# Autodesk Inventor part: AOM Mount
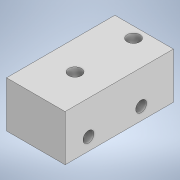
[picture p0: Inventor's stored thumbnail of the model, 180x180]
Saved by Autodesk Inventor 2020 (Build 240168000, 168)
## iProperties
Created: 2021-06
Part Number: AOM Mount
Material: Generic
Document SubType Name: Modeling
Designer: Sarah Bromley
Density: 1 g/cm^3
Appearance: Default
Author: Sarah Bromley
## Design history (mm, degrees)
sketch "Sketch1"
  geometry: L1 (-12.7, 23.5)-(12.7, 23.5); L2 (12.7, 23.5)-(12.7, -23.5); L3 (12.7, -23.5)-(-12.7, -23.5); L4 (-12.7, -23.5)-(-12.7, 23.5); L5 (-12.7, 23.5)-(12.7, -23.5); L6 (12.7, 23.5)-(-12.7, -23.5); 1 further point
  constraints: 12 end point, 2 midpoint, 2 parallel, 1 horizontal, 1 perpendicular
  dimensions: "d0" = 25.4 distance of L2.end L3.end; "d1" = 47 distance of L3.end L1.start
extrude "Extrusion1" new body sketch "Sketch1" stored distance "d2" = 20; taper "d3" = 0 deg
sketch "Sketch2"
  geometry: L1 (-12.7, -23.5)-(12.7, -23.5) reference; 2 further points
  dimensions: "d4" = 17 distance from line of point (0, -6.5) L1
hole "Hole1" sketch "Sketch2" at (0, -6.5) diameter "d5" = 3.264; stored, may be unused: countersink angle "d9" = 82 deg, drill point angle "d11" = 118 deg; dims "d6" = 6, "d7" = 5.558, "d8" = 10, "d10" = 8.8
pattern_linear "Rectangular Pattern1" dims "d14" = 25.4
sketch "Sketch3"
  geometry: L1 (0, 0)-(0, 20) reference; L2 (0, 0)-(-47, 0) reference; 2 further points
  dimensions: "d15" = 14 distance from line of L1 point (-14, 5.46); "d16" = 5.46 distance from line of L2 point (-14, 5.46)
hole "Hole2" sketch "Sketch3" at (-14, 5.46) diameter "d17" = 2.438; stored, may be unused: countersink angle "d21" = 82 deg, drill point angle "d23" = 118 deg; dims "d18" = 6, "d19" = 4.763, "d20" = 8, "d22" = 8.8
pattern_linear "Rectangular Pattern2" dims "d26" = 22.86
body "Solid1"
